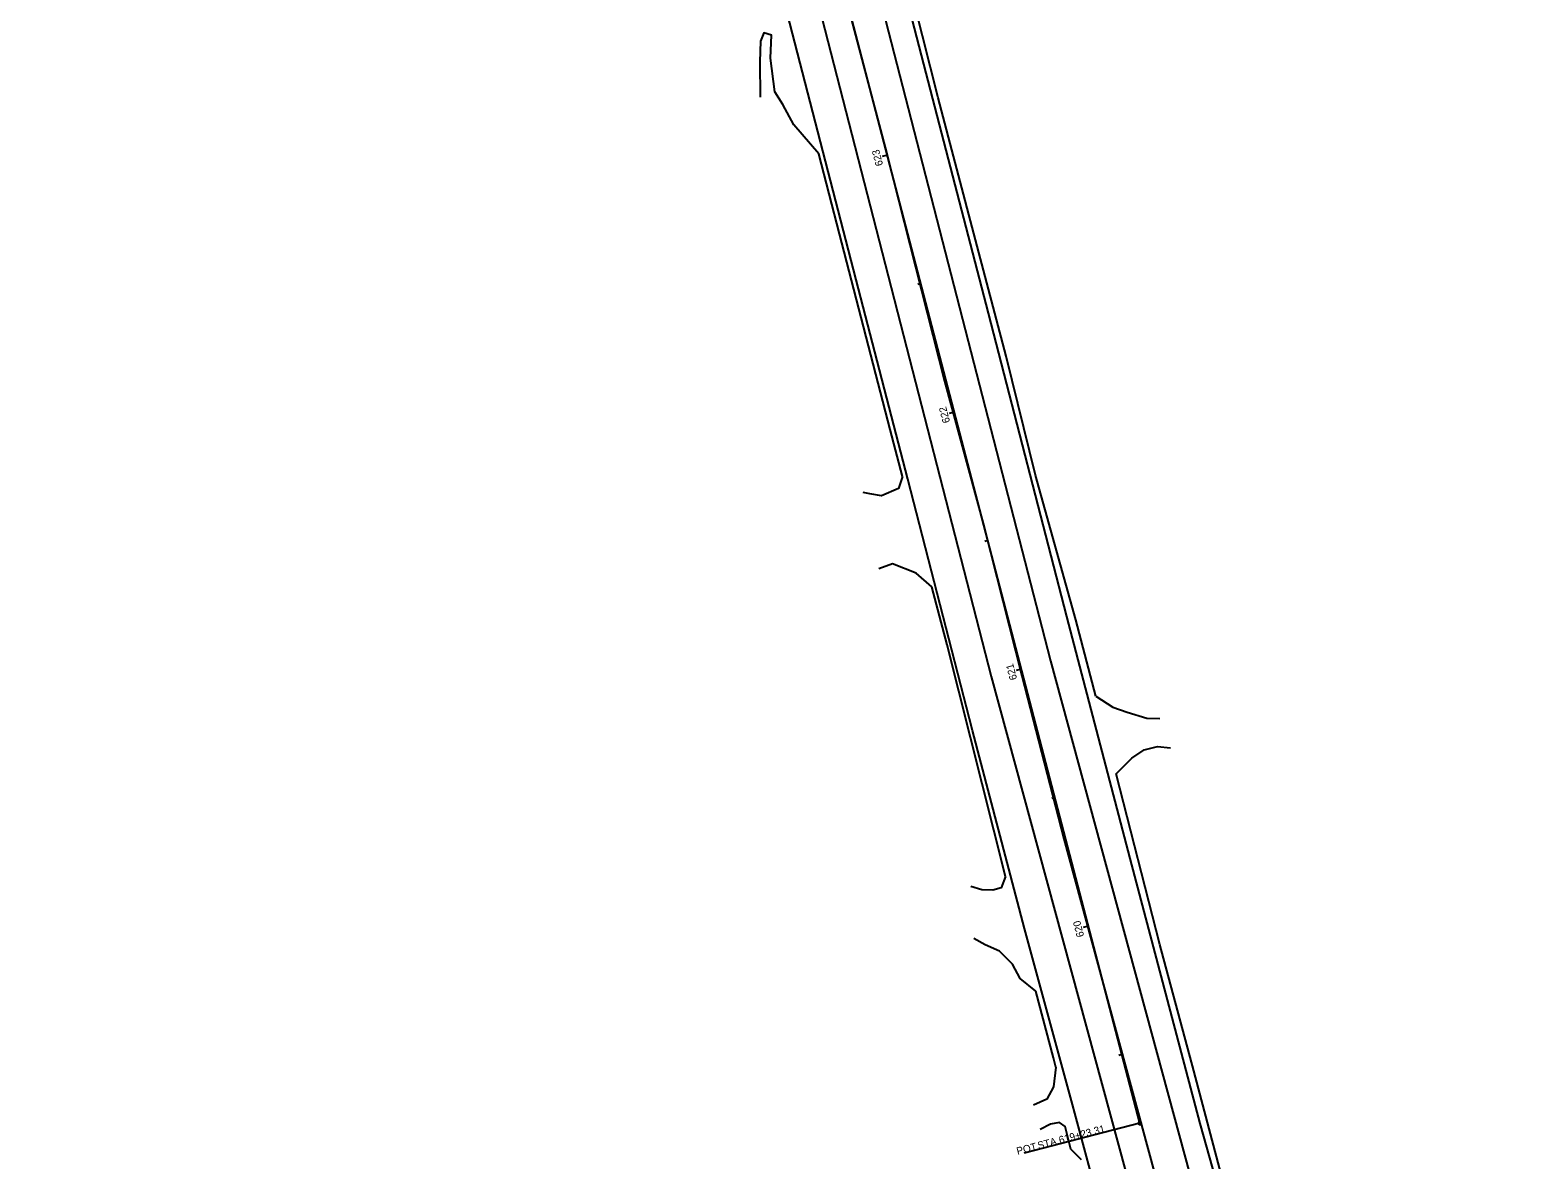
# Model space of a CAD drawing. Extents: x 171274 to 172251, y 454256 to 458569.
# Drawn here: x 171284 to 171851, y 454641 to 455066 of the extents above; entities that cross this region are included whole.
import ezdxf

# ---------------------------------------------------------------- set-up
doc = ezdxf.new("R2010")
doc.units = 0
for name, color, linetype in [('_CIVIL_CONSTRUCTION', 7, 'Continuous'), ('BR_X_Brg_Pad_Object', 7, 'Continuous'), ('BR_X_Gen_Approach_Slab', 7, 'Continuous'), ('PV_P_Saw_Cut_Line', 7, 'Continuous'), ('SC_Scratch2', 7, 'Continuous'), ('SC_Scratch4', 7, 'Continuous'), ('UT_X_Water_Cells', 7, 'Continuous'), ('VG_X_Shrub_Line_Lt', 7, 'Continuous')]:
    doc.layers.add(name, color=color, linetype=linetype)

msp = doc.modelspace()

# ---------------------------------------------------------------- linework, layer by layer
at = {"layer": '_CIVIL_CONSTRUCTION'}
for q in [(171283.69, 456257.09), (171395.21, 455829.41)]:
    msp.add_line((171701.51, 454654.7), q, dxfattribs=at)
at = {"layer": 'BR_X_Brg_Pad_Object'}
for points in [[(171754.03, 454407.86), (171735.92, 454461.96), (171723.94, 454498.82), (171703.07, 454565.09), (171686.66, 454622.59), (171676.14, 454661.67), (171658.11, 454727.95), (171638.56, 454802.49), (171614.12, 454897.2), (171594.66, 454972.24), (171569.68, 455068.83), (171549.4, 455147.21), (171527.32, 455231.4), (171503.18, 455323.76), (171475.49, 455432.87)], [(171851.36, 454270.04), (171826.95, 454336.46), (171804.15, 454399.96), (171781.51, 454465.56), (171759.43, 454534.2), (171739.13, 454601.5), (171724.17, 454654.59), (171697.86, 454754.34), (171674.05, 454845.45), (171644.56, 454959.64), (171620.14, 455053.46), (171602.68, 455120.89), (171578.31, 455214), (171552.92, 455312.25), (171527.2, 455411.62)]]:
    msp.add_lwpolyline(points, dxfattribs=at)
at = {"layer": 'BR_X_Gen_Approach_Slab'}
msp.add_lwpolyline([(171512.39, 455380.78), (171524.4, 455333.79), (171537.46, 455283.68), (171552.29, 455227.08), (171566.86, 455170.72), (171580.41, 455117.68), (171606.22, 455019.64), (171627.99, 454934.06), (171642.91, 454879.06), (171657.04, 454823.08), (171672.85, 454761.75), (171721.65, 454581.79), (171745.19, 454504.77), (171770.62, 454429.36), (171804.38, 454335.27), (171829.88, 454266.23)], dxfattribs=at)
at = {"layer": 'PV_P_Saw_Cut_Line'}
for points in [[(171684.91, 454815.49), (171677.37, 454844.17), (171662.17, 454898.71), (171651.19, 454943.5), (171639.62, 454987.27), (171625.55, 455040.8), (171613.74, 455087.62)], [(171612.17, 454898.24), (171607.51, 454915.85), (171588.37, 454989.62), (171580.65, 455019.74)], [(171650.95, 454747.63), (171628.98, 454834.77), (171623.19, 454856.61)], [(171793.08, 454439.01), (171779.33, 454478.12), (171765.04, 454523.09), (171749.4, 454575.79), (171732.09, 454635.48), (171721.88, 454674.45), (171708.97, 454722.01), (171692.61, 454786.18)], [(171669.91, 454675.76), (171668.95, 454679.23), (171662.31, 454704.44)]]:
    msp.add_lwpolyline(points, dxfattribs=at)
at = {"layer": 'SC_Scratch2'}
for points in [[(171472.94, 455579.79), (171492.29, 455506.9), (171530.75, 455358.19), (171581.19, 455165.63), (171667.81, 454828.72), (171739.52, 454564.63), (171774.65, 454453.78), (171842.22, 454266.94)], [(171470.04, 455501.07), (171508.5, 455352.39), (171558.93, 455159.85), (171645.58, 454822.85), (171717.45, 454558.14), (171752.87, 454446.4), (171820.59, 454259.11)]]:
    msp.add_lwpolyline(points, dxfattribs=at)
at = {"layer": 'SC_Scratch4'}
msp.add_line((171701.51, 454654.7), (171657.96, 454643.35), dxfattribs=at)
msp.add_circle((171701.51, 454654.7), 0.6, dxfattribs=at)
at = {"layer": 'UT_X_Water_Cells'}
for points in [[(171580.65, 455019.74), (171571.22, 455030.6), (171567.1, 455038.25), (171564.06, 455043.05), (171562.45, 455055.73), (171562.76, 455064.36), (171559.9, 455065.22), (171558.63, 455062.09), (171558.47, 455054.32), (171558.56, 455041.03)], [(171612.17, 454898.24), (171610.6, 454893.62), (171604.26, 454890.87), (171599.79, 454891.67), (171597.39, 454892.1)], [(171623.19, 454856.61), (171617.28, 454861.78), (171608.35, 454865.34), (171603.22, 454863.43)], [(171684.91, 454815.49), (171691.36, 454811.38), (171696.79, 454809.49), (171704.18, 454807.25), (171709.01, 454807.09)], [(171692.61, 454786.18), (171698.52, 454792.08), (171703.15, 454795.3), (171708.13, 454796.53), (171713.1, 454796.04)], [(171650.95, 454747.63), (171649.28, 454743.32), (171646.11, 454742.47), (171642.04, 454742.5), (171637.84, 454743.78)], [(171662.31, 454704.44), (171656.41, 454709.1), (171653.5, 454714.58), (171648.72, 454719.51), (171643.3, 454721.9), (171638.94, 454724.28)], [(171669.91, 454675.76), (171668.95, 454668.41), (171666.51, 454663.72), (171661.49, 454661.43)], [(171679.54, 454640.88), (171675.55, 454644.91), (171673.33, 454653.41), (171671.27, 454654.89), (171667.82, 454654.3), (171664.01, 454652.25)]]:
    msp.add_lwpolyline(points, dxfattribs=at)
at = {"layer": 'VG_X_Shrub_Line_Lt'}
for p, q in [((171606.47, 455019.21), (171604.53, 455018.7)), ((171619.08, 454970.82), (171617.92, 454970.52)), ((171631.7, 454922.44), (171629.76, 454921.94)), ((171644.31, 454874.06), (171643.15, 454873.76)), ((171656.93, 454825.68), (171654.99, 454825.17)), ((171669.54, 454777.29), (171668.38, 454776.99)), ((171682.16, 454728.91), (171680.22, 454728.41)), ((171694.77, 454680.53), (171693.61, 454680.23))]:
    msp.add_line(p, q, dxfattribs=at)

# ---------------------------------------------------------------- texts
at = {"layer": 'SC_Scratch4'}
for s, p in [('619+23.31', (171671.4, 454646.89)), ('POT', (171655.48, 454642.74)), (' STA. ', (171662.38, 454644.54))]:
    msp.add_text(s, height=2.8, rotation=14.6143, dxfattribs=at).set_placement(p)
at = {"layer": 'VG_X_Shrub_Line_Lt'}
for s, p in [('623', (171604.85, 455015.48)), ('622', (171630.09, 454918.7)), ('621', (171655.32, 454821.93)), ('620', (171680.56, 454725.12))]:
    msp.add_text(s, height=2.8, rotation=104.6143, dxfattribs=at).set_placement(p)

doc.saveas('drawing.dxf')
